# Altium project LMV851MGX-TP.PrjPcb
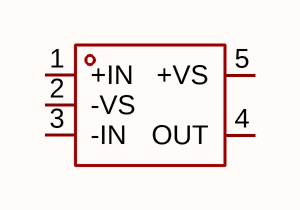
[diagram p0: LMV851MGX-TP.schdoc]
1 sheet, 1 parts. Net scope: global (net labels, ports and power ports of the same name join across sheets).

## Sheet LMV851MGX-TP.schdoc
size 127 x 101 mm

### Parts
U?  lmv851mgx-tp  [SOT-23-5_L2.9-W1.6-P0.95-LS2.8-BL]  (value not drawn)

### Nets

Not connected (* = marked no-connect by the designer): U? 1(+IN) 2(-VS) 3(-IN) 4(OUT) 5(+VS)

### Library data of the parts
U? = lmv851mgx-tp: Manufacturer: TECH PUBLIC(台舟); AddInBom: yes; ModelId: 018c57e721114987ae90467fe9f1d259; ModelTransform: 114.96,110.236,0,0,0,0,0,0,0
